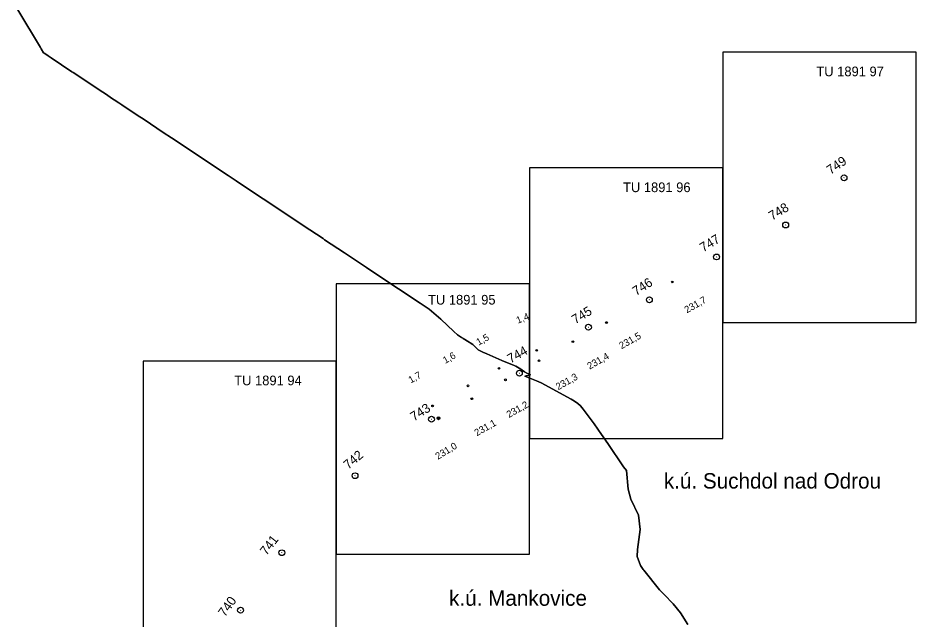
# Model space of a CAD drawing. Extents: x -661028 to -488604, y -1150850 to -1117549.
# Drawn here: x -499724 to -497400, y -1122168 to -1120612 of the extents above; entities that cross this region are included whole.
import ezdxf

# ---------------------------------------------------------------- set-up
doc = ezdxf.new("R2010")
doc.units = 0
for name, color, linetype in [('Polygon ku', 7, 'Continuous'), ('Ramecky', 7, 'Continuous'), ('Vrstva 7', 7, 'Continuous'), ('ŽBP', 7, 'Continuous')]:
    doc.layers.add(name, color=color, linetype=linetype)

# ---------------------------------------------------------------- blocks, each defined once
blk = doc.blocks.new('C513_2')
at = {"layer": 'Vrstva 7'}
blk.add_circle((0, 0), 7.5, dxfattribs=at)
blk = doc.blocks.new('C513_3')
at = {"layer": 'Vrstva 7'}
blk.add_circle((0, 0), 7.5, dxfattribs=at)
blk = doc.blocks.new('C512_2')
at = {"layer": 'Vrstva 7'}
for radius in [12.5, 7.52]:
    blk.add_circle((0, 0), radius, dxfattribs=at)

msp = doc.modelspace()

# ---------------------------------------------------------------- linework, layer by layer
at = {"layer": 'Polygon ku'}
for points in [[(-499723.8, -1120591), (-499665.8, -1120688.4), (-499663.7, -1120692), (-499657.9, -1120701.7), (-499656.3, -1120702.7), (-499649.5, -1120707.3), (-499649.2, -1120707.5), (-499645.8, -1120709.7), (-499637.6, -1120715.2), (-499584, -1120750.9), (-499580.7, -1120753.1), (-499504.6, -1120803.7), (-499494.9, -1120810.2), (-499481.5, -1120819), (-499474.5, -1120823.7), (-499462.6, -1120831.6), (-499454.8, -1120836.8), (-499415.3, -1120863.1), (-499397.6, -1120874.9), (-499347.9, -1120908), (-499326.3, -1120922.3), (-499257.8, -1120967.9), (-499238.2, -1120980.9), (-499179.7, -1121019.8), (-499159.4, -1121033.3), (-499116.5, -1121061.9), (-499061.9, -1121098.2), (-498991, -1121145.4), (-498968.3, -1121160.5), (-498934.4, -1121183), (-498930.5, -1121185.6), (-498878.8, -1121220), (-498821.7, -1121258), (-498795.4, -1121275.5), (-498682.9, -1121350.4), (-498660.2, -1121365.5), (-498629.8, -1121391.6), (-498596, -1121423.3), (-498586.7, -1121432), (-498576.5, -1121438.5), (-498572.6, -1121440.7), (-498571.6, -1121441.3), (-498556.2, -1121450.8), (-498553.7, -1121452.6), (-498547.1, -1121457.4), (-498544.3, -1121460), (-498541.8, -1121462.3), (-498532.6, -1121470.9), (-498521.2, -1121477.1), (-498511, -1121481.4), (-498471.5, -1121498.6), (-498465.8, -1121500.7), (-498454.2, -1121505.3), (-498439.7, -1121511.1), (-498435.8, -1121512.7), (-498422.9, -1121521.1), (-498419.1, -1121523.6), (-498412.7, -1121527.8), (-498406.9, -1121531.5), (-498403.1, -1121533.3), (-498397.5, -1121535.9), (-498412.5, -1121539.3), (-498382.3, -1121550.9), (-498370.3, -1121556), (-498292.4, -1121598.7), (-498284.1, -1121603.9), (-498275.2, -1121610.1), (-498268.3, -1121616.1), (-498261.3, -1121624.2), (-498233.2, -1121662.7), (-498213.6, -1121690.4), (-498197.3, -1121713.3), (-498157, -1121773.6), (-498148.9, -1121783), (-498145.2, -1121831.1), (-498137.7, -1121857.3), (-498118.5, -1121899), (-498113.4, -1121936.1), (-498120.8, -1121987.5), (-498121.3, -1122005.4), (-498113.1, -1122028.9), (-498105.9, -1122039.4), (-498104.6, -1122041), (-498064, -1122091.9), (-498056.6, -1122099.4), (-498052, -1122104), (-498028.5, -1122128.4), (-498009.1, -1122152), (-497990.2, -1122181.9)], [(-497990.2, -1122181.9), (-498009.1, -1122152), (-498028.5, -1122128.4), (-498052, -1122104), (-498056.6, -1122099.4), (-498064, -1122091.9), (-498104.6, -1122041), (-498105.9, -1122039.4), (-498113.1, -1122028.9), (-498121.3, -1122005.4), (-498120.8, -1121987.5), (-498113.4, -1121936.1), (-498118.5, -1121899), (-498137.7, -1121857.3), (-498145.2, -1121831.1), (-498148.9, -1121783), (-498157, -1121773.6), (-498197.3, -1121713.3), (-498213.6, -1121690.4), (-498233.2, -1121662.7), (-498261.3, -1121624.2), (-498268.3, -1121616.1), (-498275.2, -1121610.1), (-498284.1, -1121603.9), (-498292.4, -1121598.7), (-498370.3, -1121556), (-498382.3, -1121550.9), (-498412.5, -1121539.3), (-498397.5, -1121535.9), (-498403.1, -1121533.3), (-498406.9, -1121531.5), (-498412.7, -1121527.8), (-498419.1, -1121523.6), (-498422.9, -1121521.1), (-498435.8, -1121512.7), (-498439.7, -1121511.1), (-498454.2, -1121505.3), (-498465.8, -1121500.7), (-498471.5, -1121498.6), (-498511, -1121481.4), (-498521.2, -1121477.1), (-498532.6, -1121470.9), (-498541.8, -1121462.3), (-498544.3, -1121460), (-498547.1, -1121457.4), (-498553.7, -1121452.6), (-498556.2, -1121450.8), (-498571.6, -1121441.3), (-498572.6, -1121440.7), (-498576.5, -1121438.5), (-498586.7, -1121432), (-498596, -1121423.3), (-498629.8, -1121391.6), (-498660.2, -1121365.5), (-498682.9, -1121350.4), (-498795.4, -1121275.5), (-498821.7, -1121258), (-498878.8, -1121220), (-498930.5, -1121185.6), (-498934.4, -1121183), (-498968.3, -1121160.5), (-498991, -1121145.4), (-499061.9, -1121098.2), (-499116.5, -1121061.9), (-499159.4, -1121033.3), (-499179.7, -1121019.8), (-499238.2, -1120980.9), (-499257.8, -1120967.9), (-499326.3, -1120922.3), (-499347.9, -1120908), (-499397.6, -1120874.9), (-499415.3, -1120863.1), (-499454.8, -1120836.8), (-499462.6, -1120831.6), (-499474.5, -1120823.7), (-499481.5, -1120819), (-499494.9, -1120810.2), (-499504.6, -1120803.7), (-499580.7, -1120753.1), (-499584, -1120750.9), (-499637.6, -1120715.2), (-499645.8, -1120709.7), (-499649.2, -1120707.5), (-499649.5, -1120707.3), (-499656.3, -1120702.7), (-499657.9, -1120701.7), (-499663.7, -1120692), (-499665.8, -1120688.4), (-499723.8, -1120591)]]:
    msp.add_lwpolyline(points, dxfattribs=at)
at = {"layer": 'Ramecky'}
for points in [[(-497900, -1121400), (-497400, -1121400), (-497400, -1120700), (-497900, -1120700)], [(-498400, -1121700), (-497900, -1121700), (-497900, -1121000), (-498400, -1121000)], [(-498900, -1122000), (-498400, -1122000), (-498400, -1121300), (-498900, -1121300)], [(-499400, -1122200), (-498900, -1122200), (-498900, -1121500), (-499400, -1121500)]]:
    msp.add_lwpolyline(points, close=True, dxfattribs=at)
at = {"layer": 'Vrstva 7'}
for centre in [(-498030.6, -1121295.1), (-498201, -1121400.3)]:
    msp.add_circle(centre, 2.25, dxfattribs=at)
at = {"layer": 'ŽBP'}
for p, q in [((-497586.6, -1121025.6), (-497585.8, -1121025)), ((-497737.8, -1121147.8), (-497737, -1121147.3)), ((-497916.5, -1121230.6), (-497915.7, -1121230.1)), ((-498090.4, -1121341.4), (-498089.6, -1121340.9)), ((-498248.1, -1121412.4), (-498247.2, -1121411.9)), ((-498426.9, -1121531.4), (-498425.9, -1121531.4)), ((-498654.1, -1121650.7), (-498653.3, -1121650.1)), ((-498852, -1121797), (-498851.2, -1121796.4)), ((-499041.3, -1121996.4), (-499040.7, -1121995.6)), ((-499148.1, -1122145.3), (-499147.5, -1122144.5))]:
    msp.add_line(p, q, dxfattribs=at)
for centre in [(-497586.2, -1121025.3), (-497737.4, -1121147.6), (-497916.1, -1121230.4), (-498090, -1121341.2), (-498247.7, -1121412.2), (-498426.4, -1121531.4), (-498653.7, -1121650.4), (-498851.6, -1121796.7), (-499041, -1121996), (-499147.8, -1122144.9)]:
    msp.add_circle(centre, 7.56, dxfattribs=at)

# ---------------------------------------------------------------- block references
at = {"layer": 'Vrstva 7'}
for name, p, xscale, yscale, rotation in [('C513_3', (-498287.9, -1121449.6), 0.3, 0.3, 29.5255230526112), ('C513_3', (-498381.5, -1121472.2), 0.3, 0.30000000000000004, 29.072129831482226), ('C513_3', (-498375.5, -1121499.1), 0.30000000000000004, 0.30000000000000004, 29.545237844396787), ('C513_3', (-498479.2, -1121518.7), 0.3, 0.30000000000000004, 29.072129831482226), ('C513_3', (-498462.4, -1121548.4), 0.3, 0.30000000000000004, 29.504706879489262), ('C513_2', (-498559.2, -1121563.9), 0.3, 0.3000000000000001, 29.56044683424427), ('C513_3', (-498549.3, -1121597.5), 0.3, 0.3, 29.55242900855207), ('C513_3', (-498651, -1121616), 0.30000000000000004, 0.29999999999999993, 29.56070284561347), ('C512_2', (-498635.7, -1121647.9), 0.3, 0.3, 31.262398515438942)]:
    msp.add_blockref(name, p, dxfattribs=dict(at, xscale=xscale, yscale=yscale, rotation=rotation))

# ---------------------------------------------------------------- texts
at = {"layer": 'Polygon ku'}
for s, p in [('k.ú. Suchdol nad Odrou', (-498052.6, -1121829.9)), ('k.ú. Mankovice', (-498608.2, -1122133.4))]:
    msp.add_text(s, height=40, dxfattribs=at).set_placement(p)
at = {"layer": 'Ramecky'}
for s, p in [('TU 1891 97', (-497657.9, -1120762.5)), ('TU 1891 96', (-498158.1, -1121062.5)), ('TU 1891 95', (-498662.7, -1121353.6)), ('TU 1891 94', (-499164.2, -1121562.5))]:
    msp.add_text(s, height=25, dxfattribs=at).set_placement(p)
at = {"layer": 'Vrstva 7'}
for s, rotation, p in [('231,7', 29.5248, (-497993.1, -1121376.6)), ('1,4', 21.8411, (-498430.3, -1121403.4)), ('1,5', 29.0721, (-498531.9, -1121460.1)), ('231,5', 29.5185, (-498162, -1121469.4)), ('1,6', 29.5604, (-498618.2, -1121507.3)), ('231,4', 29.5255, (-498244.6, -1121522.2)), ('1,7', 29.5607, (-498707.3, -1121558)), ('231,3', 29.5452, (-498325.8, -1121575.6)), ('231,2', 29.5047, (-498453.5, -1121647.6)), ('231,1', 29.5524, (-498536.6, -1121694.9)), ('231,0', 31.2624, (-498637.1, -1121755.7))]:
    msp.add_text(s, height=18, rotation=rotation, dxfattribs=at).set_placement(p)
at = {"layer": 'ŽBP'}
for s, rotation, p in [('749', 34.4886, (-497621.1, -1121017.9)), ('748', 31.4056, (-497772.3, -1121136.7)), ('747', 31.1638, (-497950.6, -1121218.5)), ('746', 33.0815, (-498124.1, -1121331.7)), ('745', 31.6472, (-498281.5, -1121405)), ('744', 29.6192, (-498449.2, -1121506.5)), ('743', 32.6879, (-498699, -1121656.5)), ('742', 40.156, (-498869.1, -1121781.5)), ('741', 52.3891, (-499080.8, -1122004.6)), ('740', 54.2673, (-499188.3, -1122163.7))]:
    msp.add_text(s, height=24, rotation=rotation, dxfattribs=at).set_placement(p)

doc.saveas('drawing.dxf')
